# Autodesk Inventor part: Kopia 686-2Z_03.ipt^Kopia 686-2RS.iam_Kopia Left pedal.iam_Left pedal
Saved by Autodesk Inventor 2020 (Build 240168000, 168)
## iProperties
Created: 2017-10
Part Number: Kopia 686-2Z_03.ipt^Kopia 686-2RS.iam_Kopia Left pedal.iam_Left pedal
Material: Ogólny
Document SubType Name: Modeling
Designer: Tomasz
Density: 1 g/cm^3
Appearance: Domyślna
Sending System: SolidWorks 2017
Last Author: Tomasz
Last Saved: 2017-10-01
Author: Tomasz
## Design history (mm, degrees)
